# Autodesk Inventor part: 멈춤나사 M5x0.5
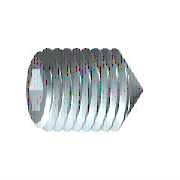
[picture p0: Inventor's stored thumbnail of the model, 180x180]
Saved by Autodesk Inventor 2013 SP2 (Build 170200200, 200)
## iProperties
Company: 한국ATC센터
IsCustomPart: 1
Created: 2014-10
Part Number: 멈춤나사 M5x0.5
Material: 강, 연강
Description: 6각 소켓 머리 없는 멈춤 나사
Document SubType Name: Modeling
Standard: KS B 1028
Designer: 한국ATC센터
Standards Organization: KS
Language: ko-KR
Size Designation: 원추점 M5x10
Categories: <MemberInstance><Categories><Category DisplayName="조임쇠" InternalName="e4da775c-781d-43d5-af7c-5136215cf5a6" Mnemonic="FSTN"><Category DisplayName="볼트" InternalN
Density: 7.86 g/cm^3
Mass: 1.16912 g
Surface Area: 1.91683 cm^2
Volume: 0.148743 cm^3
Author: KYOUNG IL JANG
Revision Number: 1
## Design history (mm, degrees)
sketch "스케치1"
  geometry: L1 (0, 0)-(6.167, 0); L2 (10, 1.443)-(10, 2.5); L3 (10, 2.5)-(0, 2.5); L4 (10, 1.443)-(7, 1.443); L5 (7, 1.443)-(6.167, 0); L6 (0, -0.5)-(0, 3) reference; L7 (0, 2.5)-(0, 0)
  constraints: 13 end point, 3 parallel, 1 collinear, 1 perpendicular, 1 point on line
  dimensions: "d0" = 3 distance of L2.start L4.end (= INTI); "d1" = 60 deg angle of L5 L1; "d2" = 5 diameter of L3 L1 (= NND); "d3" = 2.88675 diameter of L4 L1 (= 1.1547 x SW); "d5" = 10 distance from line of L2 L3.end (= NLG)
revolve "본체" sketch "스케치1" stored, may be unused: angle "d6" = 90 deg
sketch "스케치2"
  geometry: L1 (-0.722, 1.25)-(0.722, 1.25); L2 (0.722, 1.25)-(1.443, 0); L3 (1.443, 0)-(0.722, -1.25); L4 (0.722, -1.25)-(-0.722, -1.25); L5 (-0.722, -1.25)-(-1.443, 0); L6 (-1.443, 0)-(-0.722, 1.25); 3 further points
  constraints: 12 end point, 1 coincident, 1 horizontal, 13 other
extrude "슬롯" join sketch "스케치2" taper "d7" = 0 deg; stored distance "d21" = 10
workaxis "Work Axis1"
workplane "Work Plane1"
body "Solid1"
feature "스레드" dims "d12" = 10 (= NLG), "d13" = 0
chamfer "모따기1" distance "d8" = 2.25 (computed from NND, SPD, FAWI); stored, may be unused: angle "d9" = 45 deg (= FAWI), second distance "d34" = 2.25 (computed from NND, SPD, FAWI)
chamfer "모따기2" distance "d10" = 0.49076 (= -0.5 x GD1 + 0.5 x NND); stored, may be unused: angle "d11" = 45 deg (= FAWI), second distance "d35" = 0.49076 (= -0.5 x GD1 + 0.5 x NND)
other parameters: "NND" = 5 [user parameter; used in 5 equation terms], "NLG" = 10 [user parameter; used in 2 equation terms], "INTI" = 3 [user parameter; used in 1 equation term], "FAWI" = 45 deg [user parameter; used in 4 equation terms], "SW" = 2.5 [user parameter; used in 2 equation terms], "GD1" = 4.01848 (= THREADDIA - 1.2269 x PTC) [user parameter; used in 2 equation terms], "d4" = 0, "FAWI1" = 45 deg [user parameter], "SPD" = 0.5 [user parameter; used in 2 equation terms], "d36" = 0, "d37" = 0, "GUL" = 0.49076 (= 0.61345 x PTC) [user parameter], "TPU" = 12.5 (computed from PTC) [user parameter], "TOA" = 30 deg [user parameter], "THREADDIA" = 5 [user parameter; used in 1 equation term], "PTC" = 0.8 [user parameter; used in 4 equation terms], "GAL" = 0.49076 (= 0.61345 x PTC) [user parameter], "E0" = 2.8875 (= 1.155 x SW) [user parameter]
